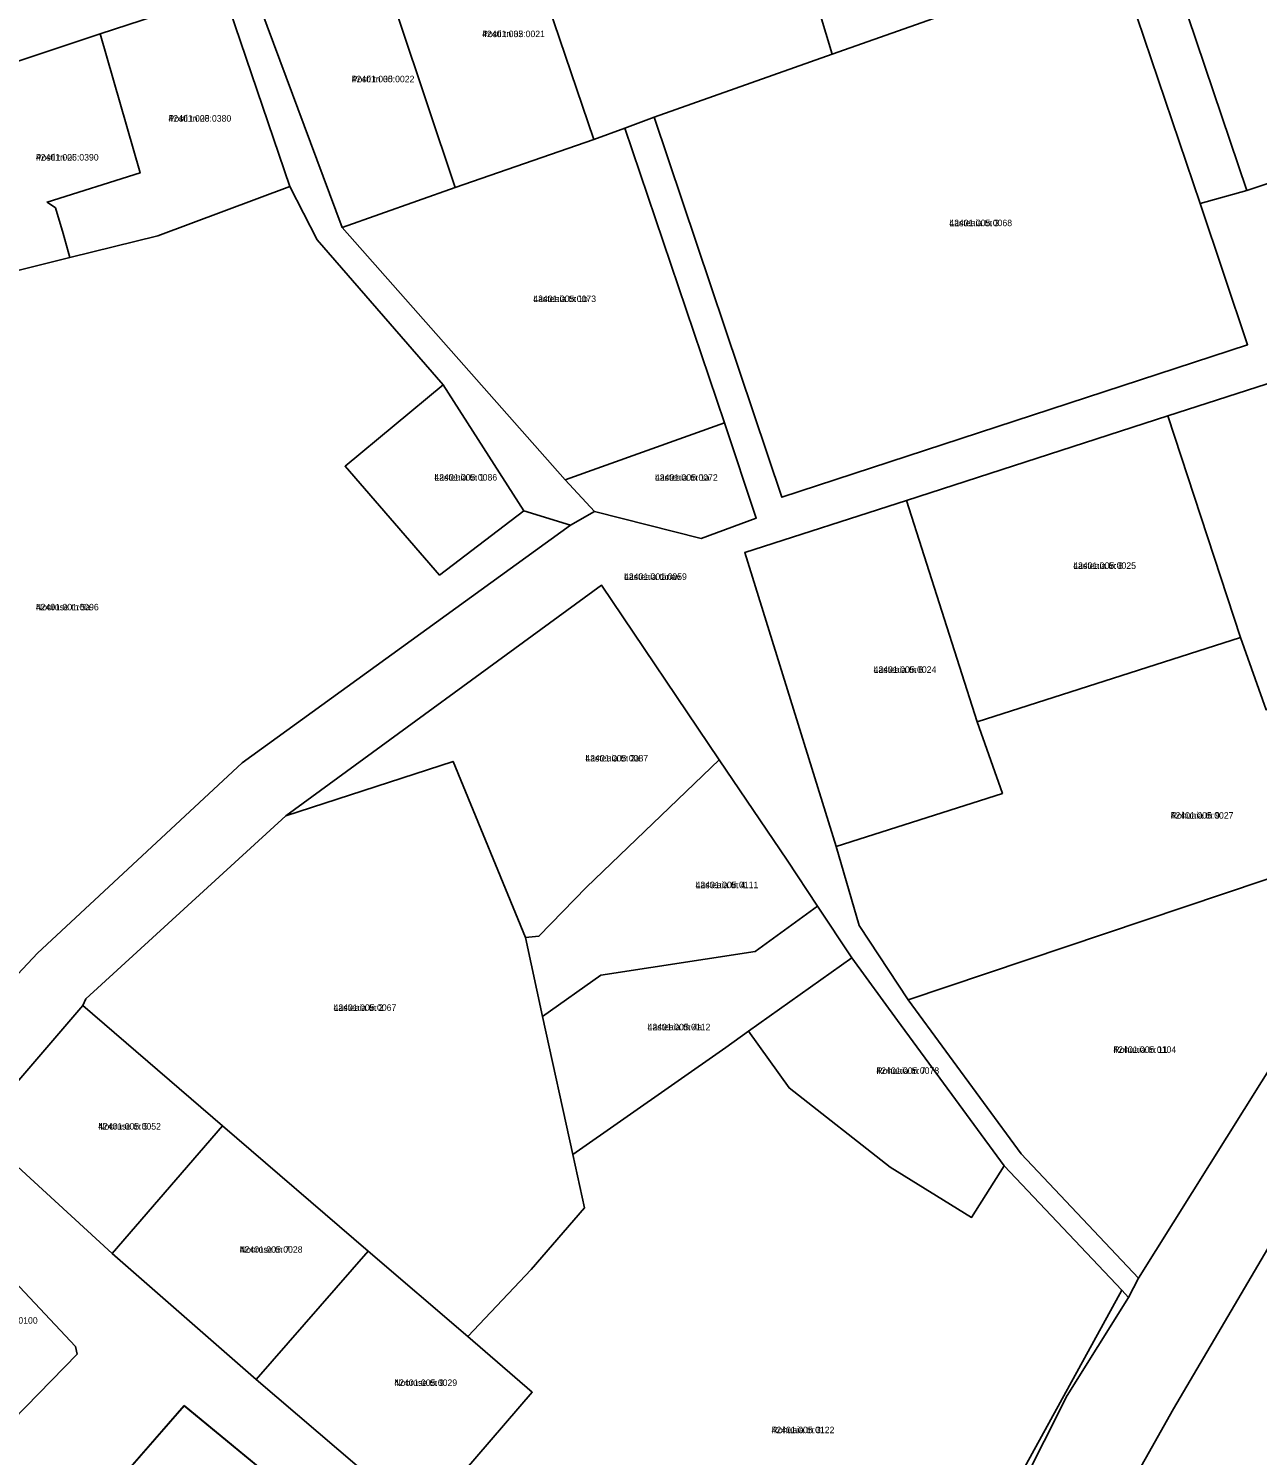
# Model space of a CAD drawing. Extents: x 595979 to 597983, y 6604231 to 6607350.
# Drawn here: x 597430.6 to 597714.5, y 6606228.5 to 6606558.1 of the extents above; entities that cross this region are included whole.
import ezdxf

# ---------------------------------------------------------------- set-up
doc = ezdxf.new("R2010")
doc.units = 0
for name, color, linetype in [('L_AADRESS', 7, 'Continuous'), ('PIIR', 7, 'Continuous'), ('TUNNUS', 7, 'Continuous')]:
    doc.layers.add(name, color=color, linetype=linetype)

msp = doc.modelspace()

# ---------------------------------------------------------------- linework, layer by layer
at = {"layer": 'PIIR'}
for points in [[(597568.59, 6606600.02), (597617.92, 6606616.81), (597627.8, 6606584.54), (597635.47, 6606587.26), (597643.81, 6606561.92), (597616.25, 6606552.17), (597608.42, 6606578.08), (597578.83, 6606567.87)], [(597682.91, 6606606.97), (597716.73, 6606617.61), (597746.05, 6606532.03), (597711.99, 6606520.69)], [(597541.38, 6606590.75), (597568.59, 6606600.02), (597578.83, 6606567.87), (597608.42, 6606578.08), (597616.25, 6606552.17), (597575.11, 6606537.67), (597568.32, 6606535.1), (597561.14, 6606532.48)], [(597509.62, 6606579.92), (597541.36, 6606590.73), (597561.14, 6606532.48), (597529.16, 6606521.4)], [(597503.02, 6606512.14), (597481.32, 6606570.54), (597509.62, 6606579.92), (597529.16, 6606521.4)], [(597575.11, 6606537.67), (597616.25, 6606552.17), (597643.81, 6606561.92), (597681.85, 6606575.06), (597701.21, 6606517.72), (597712.18, 6606485.07), (597604.59, 6606449.84)], [(597456.39, 6606524.74), (597447.13, 6606556.9), (597475.79, 6606566.26), (597490.98, 6606521.6), (597460.45, 6606510.21), (597440.14, 6606505.19), (597438.63, 6606510.78), (597436.81, 6606516.67), (597434.89, 6606518)], [(597414.73, 6606498.88), (597408.21, 6606543.96), (597447.13, 6606556.9), (597456.39, 6606524.74), (597434.89, 6606518), (597436.81, 6606516.67), (597438.63, 6606510.78), (597440.14, 6606505.19)], [(597503.02, 6606512.14), (597529.16, 6606521.4), (597561.14, 6606532.48), (597568.32, 6606535.1), (597591.35, 6606467.02), (597554.57, 6606453.87)], [(597421.94, 6606469.06), (597414.73, 6606498.88), (597440.14, 6606505.19), (597460.45, 6606510.21), (597490.98, 6606521.6), (597497.25, 6606509.28), (597526.35, 6606475.79), (597503.72, 6606456.98), (597525.56, 6606431.86), (597544.98, 6606446.72), (597555.81, 6606443.42), (597479.92, 6606388.47), (597432.66, 6606344.54), (597405, 6606315.04), (597308.82, 6606394.53), (597342.93, 6606406.67), (597352.48, 6606403.76), (597355.41, 6606401.16), (597363.55, 6606385.72), (597374.14, 6606395), (597420.74, 6606446.26), (597422.14, 6606461.42)], [(597525.56, 6606431.86), (597503.72, 6606456.98), (597526.35, 6606475.79), (597544.98, 6606446.72)], [(597693.79, 6606468.64), (597718.88, 6606476.75), (597740.87, 6606408.48), (597716.44, 6606400.74), (597710.55, 6606417.45)], [(597554.57, 6606453.87), (597591.35, 6606467.02), (597598.71, 6606445.03), (597585.97, 6606440.29), (597561.36, 6606446.55)], [(597633.38, 6606449.08), (597693.79, 6606468.64), (597710.55, 6606417.45), (597649.74, 6606397.94)], [(597596.05, 6606437.06), (597633.38, 6606449.08), (597649.74, 6606397.94), (597655.54, 6606381.43), (597617.16, 6606369.13)], [(597490.04, 6606376.21), (597562.95, 6606429.5), (597590.16, 6606389.18), (597559.45, 6606359.8), (597548.5, 6606348.42), (597545.36, 6606348.1), (597528.68, 6606388.81)], [(597617.16, 6606369.13), (597655.54, 6606381.43), (597649.74, 6606397.94), (597710.55, 6606417.45), (597716.44, 6606400.74), (597740.87, 6606408.48), (597752.2, 6606373.52), (597633.81, 6606333.73), (597622.49, 6606350.88)], [(597443.12, 6606332.4), (597443.82, 6606333.96), (597490.04, 6606376.21), (597528.68, 6606388.81), (597545.36, 6606348.1), (597549.33, 6606329.87), (597556.31, 6606297.98), (597559, 6606285.67), (597546.69, 6606271.47), (597532.05, 6606255.96), (597509.04, 6606275.71), (597475.43, 6606304.6)], [(597545.36, 6606348.1), (597548.5, 6606348.42), (597559.45, 6606359.8), (597590.16, 6606389.18), (597605.84, 6606366.03), (597612.87, 6606355.41), (597598.42, 6606344.88), (597562.79, 6606339.47), (597549.33, 6606329.87)], [(597633.81, 6606333.73), (597752.2, 6606373.52), (597686.96, 6606269.47), (597659.89, 6606298.14)], [(597549.33, 6606329.87), (597562.79, 6606339.47), (597598.42, 6606344.88), (597612.87, 6606355.41), (597620.77, 6606343.45), (597596.91, 6606326.51), (597591.7, 6606322.73), (597556.31, 6606297.98)], [(597620.77, 6606343.45), (597631.33, 6606328.95), (597639.37, 6606317.98), (597655.95, 6606295.37), (597648.41, 6606283.48), (597629.59, 6606295.1), (597606.29, 6606313.4), (597596.91, 6606326.51)], [(597418.56, 6606303.86), (597443.12, 6606332.4), (597475.43, 6606304.6), (597449.96, 6606275.13)], [(597556.31, 6606297.98), (597591.7, 6606322.73), (597596.91, 6606326.51), (597606.29, 6606313.4), (597629.59, 6606295.1), (597648.41, 6606283.48), (597655.95, 6606295.37), (597683.1, 6606266.67), (597613.25, 6606139.32), (597521.38, 6606213.37), (597546.95, 6606243.09), (597532.05, 6606255.96), (597546.69, 6606271.47), (597559, 6606285.67)], [(597449.96, 6606275.13), (597475.43, 6606304.6), (597509.04, 6606275.71), (597483.22, 6606246.01)], [(597413.23, 6606283.67), (597441.43, 6606253.64), (597441.82, 6606251.9), (597423.91, 6606233.57), (597394.62, 6606264.1)], [(597483.22, 6606246.01), (597509.04, 6606275.71), (597532.05, 6606255.96), (597546.95, 6606243.09), (597521.38, 6606213.37)], [(597683.1, 6606266.67), (597684.7, 6606264.98), (597670.49, 6606242.36), (597617.1, 6606136.22), (597613.25, 6606139.32)], [(597466.52, 6606240.01), (597520.92, 6606195.21), (597510.19, 6606189.12), (597489.89, 6606169.48), (597442.87, 6606212.74)]]:
    msp.add_lwpolyline(points, close=True, dxfattribs=at)
for points in [[(597682.91, 6606606.97), (597711.99, 6606520.69), (597701.21, 6606517.72), (597681.85, 6606575.06)], [(597565.06, 6606039.67), (597587.91, 6606081.73), (597610.46, 6606123.21), (597617.1, 6606136.22), (597670.49, 6606242.36), (597684.7, 6606264.98), (597686.96, 6606269.47), (597752.2, 6606373.52), (597761.45, 6606387.69), (597839.67, 6606514.5), (597852.82, 6606538.23), (597878.8, 6606591.86)], [(597898.31, 6606579.37), (597873.37, 6606529.02), (597844.57, 6606480.97), (597827.98, 6606455.52), (597806.07, 6606421.26), (597786.61, 6606390.85), (597779.47, 6606379.69), (597729.41, 6606297.64), (597695.07, 6606239.29), (597655.09, 6606168.29), (597622.28, 6606110.03), (597610.7, 6606083.09), (597599, 6606056.25), (597583.97, 6606026)], [(597481.32, 6606570.54), (597503.02, 6606512.14), (597554.57, 6606453.87), (597561.36, 6606446.55), (597555.81, 6606443.42), (597544.98, 6606446.72), (597526.35, 6606475.79), (597497.25, 6606509.28), (597490.98, 6606521.6), (597475.79, 6606566.26), (597447.13, 6606556.9), (597408.21, 6606543.96)], [(597405, 6606315.04), (597432.66, 6606344.54), (597479.92, 6606388.47), (597555.81, 6606443.42), (597561.36, 6606446.55), (597585.97, 6606440.29), (597598.71, 6606445.03), (597591.35, 6606467.02), (597568.32, 6606535.1), (597575.11, 6606537.67), (597604.59, 6606449.84), (597712.18, 6606485.07), (597701.21, 6606517.72), (597711.99, 6606520.69), (597746.05, 6606532.03), (597790.29, 6606546.25), (597853.26, 6606565.17)], [(597718.88, 6606476.75), (597693.79, 6606468.64), (597633.38, 6606449.08), (597596.05, 6606437.06), (597617.16, 6606369.13), (597622.49, 6606350.88), (597633.81, 6606333.73), (597659.89, 6606298.14), (597686.96, 6606269.47), (597684.7, 6606264.98), (597683.1, 6606266.67), (597655.95, 6606295.37), (597639.37, 6606317.98), (597631.33, 6606328.95), (597620.77, 6606343.45), (597612.87, 6606355.41), (597605.84, 6606366.03), (597590.16, 6606389.18), (597562.95, 6606429.5), (597490.04, 6606376.21), (597443.82, 6606333.96), (597443.12, 6606332.4), (597418.56, 6606303.86)], [(597418.56, 6606303.86), (597449.96, 6606275.13), (597483.22, 6606246.01), (597521.38, 6606213.37), (597613.25, 6606139.32), (597617.1, 6606136.22), (597610.46, 6606123.21), (597520.92, 6606195.21), (597466.55, 6606239.93), (597442.87, 6606212.74), (597323.41, 6606074.19)], [(597423.91, 6606233.57), (597441.82, 6606251.9), (597441.43, 6606253.64), (597413.23, 6606283.67)]]:
    msp.add_lwpolyline(points, dxfattribs=at)

# ---------------------------------------------------------------- texts
at = {"layer": 'L_AADRESS'}
for s, p in [('Posti tn 32', (597535.38, 6606556.12)), ('Posti tn 30', (597505.24, 6606545.7)), ('Posti tn 28', (597462.93, 6606536.6)), ('Posti tn 26', (597432.3, 6606527.61)), ('Lasteaia tn 3', (597643.28, 6606512.45)), ('Lasteaia tn 1b', (597547.19, 6606494.93)), ('Lasteaia tn 1', (597524.35, 6606453.69)), ('Lasteaia tn 1a', (597575.3, 6606453.65)), ('Lasteaia tn 8', (597671.9, 6606433.29)), ('Lasteaia tänav', (597568.16, 6606430.75)), ('Nooruse tn 5a', (597432.32, 6606423.71)), ('Lasteaia tn 6', (597625.79, 6606409.27)), ('Lasteaia tn 2a', (597559.22, 6606388.8)), ('Rohuaia tn 9', (597694.42, 6606375.59)), ('Lasteaia tn 4', (597584.67, 6606359.53)), ('Lasteaia tn 2', (597501.06, 6606331.19)), ('Lasteaia tn 4a', (597573.6, 6606326.7)), ('Rohuaia tn 11', (597681.18, 6606321.49)), ('Rohuaia tn 7', (597626.43, 6606316.63)), ('Nooruse tn 5', (597446.69, 6606303.76)), ('Nooruse tn 7', (597479.4, 6606275.31)), ('Nooruse tn 9', (597515.1, 6606244.54)), ('Rohuaia tn 3', (597602.24, 6606233.63))]:
    msp.add_text(s, height=1.5, dxfattribs=at).set_placement(p)
at = {"layer": 'TUNNUS'}
for s, p in [('42401:005:0021', (597535.38, 6606556.12)), ('42401:005:0022', (597505.24, 6606545.7)), ('42401:005:0380', (597462.93, 6606536.6)), ('42401:005:0390', (597432.3, 6606527.61)), ('42401:005:0068', (597643.28, 6606512.45)), ('42401:005:0073', (597547.19, 6606494.93)), ('42401:005:0086', (597524.35, 6606453.69)), ('42401:005:0072', (597575.3, 6606453.65)), ('42401:005:0025', (597671.9, 6606433.29)), ('42401:001:0059', (597568.16, 6606430.75)), ('42401:001:0096', (597432.32, 6606423.71)), ('42401:005:0024', (597625.79, 6606409.27)), ('42401:005:0087', (597559.22, 6606388.8)), ('42401:005:0027', (597694.42, 6606375.59)), ('42401:005:0111', (597584.67, 6606359.53)), ('42401:005:0067', (597501.06, 6606331.19)), ('42401:005:0112', (597573.6, 6606326.7)), ('42401:005:0104', (597681.18, 6606321.49)), ('42401:005:0078', (597626.43, 6606316.63)), ('42401:005:0052', (597446.69, 6606303.76)), ('42401:005:0028', (597479.4, 6606275.31)), ('42401:005:0100', (597418.22, 6606258.93)), ('42401:005:0029', (597515.1, 6606244.54)), ('42401:005:0122', (597602.24, 6606233.63))]:
    msp.add_text(s, height=1.5, dxfattribs=at).set_placement(p)

doc.saveas('drawing.dxf')
